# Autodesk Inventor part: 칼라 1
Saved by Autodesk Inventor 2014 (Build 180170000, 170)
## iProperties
Created: 2025-12
Part Number: 칼라 1
Material: 일반
Document SubType Name: Modeling
Designer: dg
Density: 1 g/cm^3
Appearance: 기본값
Author: dg
Author: jhkim
Creation Date: 2025-11-19
Sending System: Autodesk Inventor 2026
Preprocessor: ST-DEVELOPER v20.1
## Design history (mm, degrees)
node "칼라 11"
node "솔리드1"
node "기준1"
